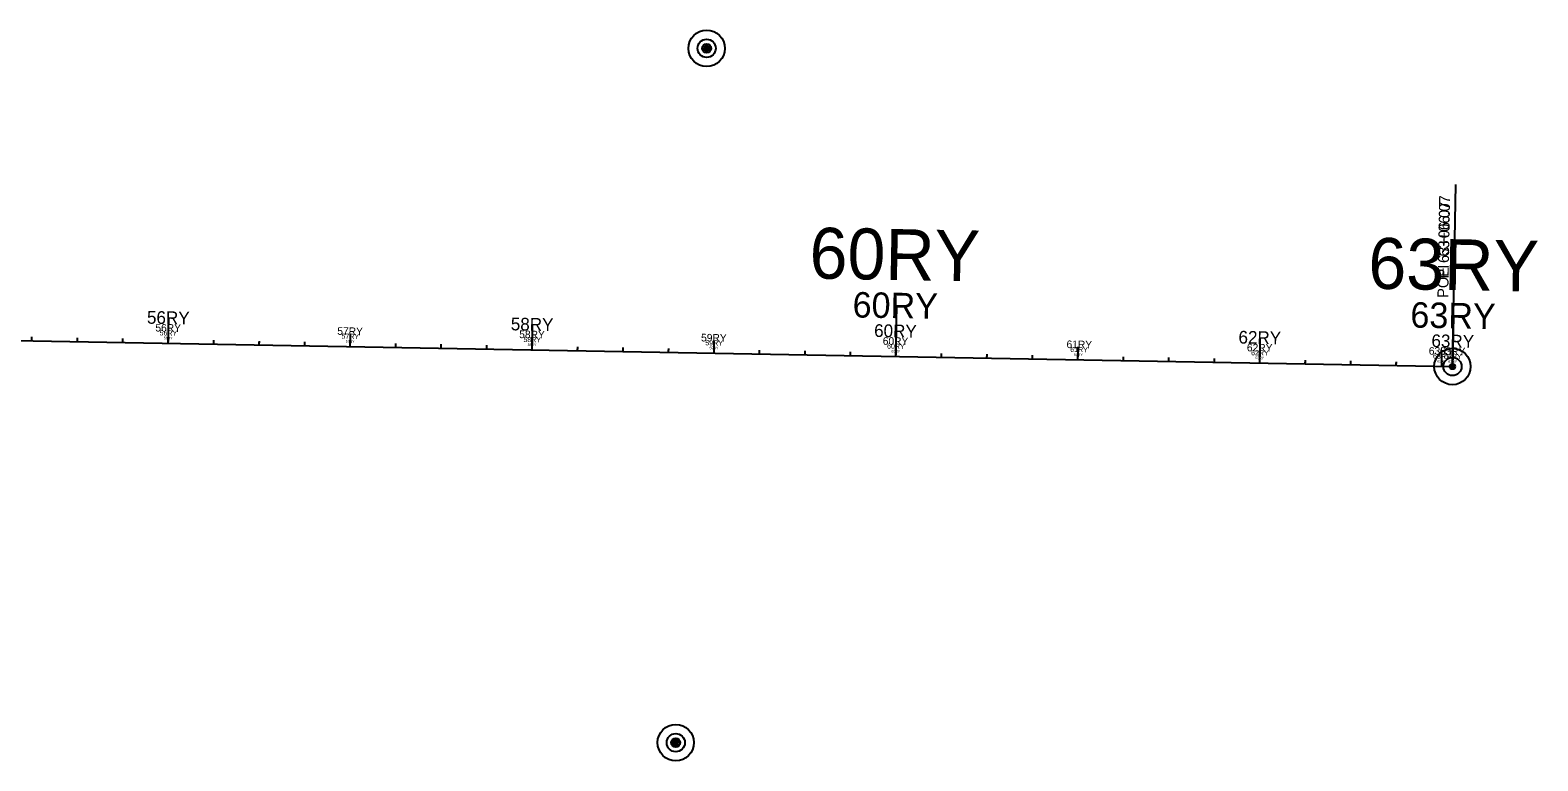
# Model space of a CAD drawing. Extents: x 564646 to 607088, y 225853 to 261760.
# Drawn here: x 599053 to 599882, y 238789 to 239190 of the extents above; entities that cross this region are included whole.
import ezdxf

# ---------------------------------------------------------------- set-up
doc = ezdxf.new("R2010")
doc.units = 0
for name, color, linetype in [('B_CONC_HIDDEN_LT', 7, 'Continuous'), ('B_CONST', 7, 'Continuous'), ('B_EXIST', 7, 'Continuous'), ('B_TEXT', 7, 'Continuous'), ('E-Easements', 7, 'Continuous'), ('E-Property Lines', 7, 'Continuous'), ('E_ALI_100', 7, 'Continuous'), ('E_RW_CorporateLimits', 7, 'Continuous'), ('E_RW_EasementUtility_Text', 7, 'Continuous'), ('E_WTR_FlowLine', 7, 'Continuous'), ('EMCS_SURVEY_PT CODES', 7, 'Continuous'), ('EMCS_SURVEY_PT ELEV', 7, 'Continuous'), ('EMCS_SURVEY_PT NOTES', 7, 'Continuous'), ('Level 33', 7, 'Continuous'), ('P-Easements Floodplain', 7, 'Continuous'), ('P-Easements Temporary', 7, 'Continuous'), ('P_ALI_100_Tic', 7, 'Continuous'), ('P_ALI_20', 7, 'Continuous'), ('P_ALI_50', 7, 'Continuous'), ('P_RW_AccessPreviousProject Txt', 7, 'Continuous'), ('P_RW_EasementPerm', 7, 'Continuous'), ('P_RW_PropertyConnector', 7, 'Continuous'), ('P_RW_Proposed', 7, 'Continuous'), ('P_WAL', 7, 'Continuous')]:
    doc.layers.add(name, color=color, linetype=linetype)

msp = doc.modelspace()

# ---------------------------------------------------------------- linework, layer by layer
at = {"layer": 'B_CONC_HIDDEN_LT'}
msp.add_line((597176.17, 239053.94), (599834.96, 239005.61), dxfattribs=at)
at = {"layer": 'B_CONST'}
for centre in [(599425.03, 239180.5), (599425.03, 239180.5), (599834.96, 239005.61), (599834.96, 239005.61), (599408.09, 238798.86), (599408.09, 238798.86)]:
    msp.add_circle(centre, 1.5, dxfattribs=at)
at = {"layer": 'B_EXIST'}
for centre in [(599425.03, 239180.5), (599834.96, 239005.61), (599408.09, 238798.86)]:
    msp.add_circle(centre, 5, dxfattribs=at)
at = {"layer": 'B_TEXT'}
msp.add_lwpolyline([(599834.96, 239005.61), (599836.78, 239105.59)], dxfattribs=at)
at = {"layer": 'E-Easements'}
for centre in [(599425.03, 239180.5), (599408.09, 238798.86)]:
    msp.add_circle(centre, 2.5, dxfattribs=at)
at = {"layer": 'E_ALI_100'}
for points in [[(599054.05, 239021.21), (599054.02, 239019.81)], [(599079.04, 239020.75), (599079.02, 239019.35)], [(599104.04, 239020.3), (599104.01, 239018.9)], [(599129.06, 239021.24), (599129.01, 239018.44)], [(599154.03, 239019.39), (599154, 239017.99)], [(599179.02, 239018.93), (599179, 239017.53)], [(599229.04, 239019.42), (599228.99, 239016.62)], [(599204.02, 239018.48), (599204, 239017.08)], [(599254.01, 239017.57), (599253.99, 239016.17)], [(599279.01, 239017.12), (599278.98, 239015.72)], [(599304, 239016.66), (599303.98, 239015.26)], [(599329.03, 239017.61), (599328.97, 239014.81)], [(599354, 239015.75), (599353.97, 239014.35)], [(599378.99, 239015.3), (599378.97, 239013.9)], [(599403.99, 239014.84), (599403.96, 239013.44)], [(599429.01, 239015.79), (599428.96, 239012.99)], [(599453.98, 239013.94), (599453.95, 239012.54)], [(599478.98, 239013.48), (599478.95, 239012.08)], [(599503.97, 239013.03), (599503.95, 239011.63)], [(599528.99, 239013.97), (599528.94, 239011.17)], [(599553.96, 239012.12), (599553.94, 239010.72)], [(599578.96, 239011.66), (599578.93, 239010.26)], [(599603.95, 239011.21), (599603.93, 239009.81)], [(599628.98, 239012.15), (599628.92, 239009.36)], [(599653.95, 239010.3), (599653.92, 239008.9)], [(599678.94, 239009.85), (599678.92, 239008.45)], [(599703.94, 239009.39), (599703.91, 239007.99)], [(599728.96, 239010.34), (599728.91, 239007.54)], [(599753.93, 239008.48), (599753.9, 239007.08)], [(599778.93, 239008.03), (599778.9, 239006.63)], [(599803.92, 239007.57), (599803.9, 239006.17)], [(599828.94, 239008.52), (599828.89, 239005.72)], [(599835.01, 239008.41), (599834.96, 239005.61)], [(599834.99, 239007.01), (599834.96, 239005.61)]]:
    msp.add_lwpolyline(points, dxfattribs=at)
at = {"layer": 'E_WTR_FlowLine'}
for centre in [(599425.03, 239180.5), (599834.96, 239005.61), (599408.09, 238798.86)]:
    msp.add_circle(centre, 0.5, dxfattribs=at)
at = {"layer": 'EMCS_SURVEY_PT CODES'}
msp.add_line((597176.17, 239053.94), (599834.96, 239005.61), dxfattribs=at)
at = {"layer": 'EMCS_SURVEY_PT ELEV'}
msp.add_line((597176.17, 239053.94), (599834.96, 239005.61), dxfattribs=at)
msp.add_line((597176.17, 239053.94), (599834.96, 239005.61), dxfattribs=at)
at = {"layer": 'Level 33'}
for points in [[(599054.03, 239020.51), (599054.02, 239019.81)], [(599079.03, 239020.05), (599079.02, 239019.35)], [(599104.02, 239019.6), (599104.01, 239018.9)], [(599129.03, 239019.84), (599129.01, 239018.44)], [(599154.02, 239018.69), (599154, 239017.99)], [(599179.01, 239018.23), (599179, 239017.53)], [(599204.01, 239017.78), (599204, 239017.08)], [(599229.02, 239018.02), (599228.99, 239016.62)], [(599254, 239016.87), (599253.99, 239016.17)], [(599279, 239016.42), (599278.98, 239015.72)], [(599303.99, 239015.96), (599303.98, 239015.26)], [(599329, 239016.21), (599328.97, 239014.81)], [(599353.98, 239015.05), (599353.97, 239014.35)], [(599378.98, 239014.6), (599378.97, 239013.9)], [(599403.97, 239014.14), (599403.96, 239013.44)], [(599428.98, 239014.39), (599428.96, 239012.99)], [(599453.97, 239013.24), (599453.95, 239012.54)], [(599478.96, 239012.78), (599478.95, 239012.08)], [(599503.96, 239012.33), (599503.95, 239011.63)], [(599528.97, 239012.57), (599528.94, 239011.17)], [(599553.95, 239011.42), (599553.94, 239010.72)], [(599578.95, 239010.96), (599578.93, 239010.26)], [(599628.95, 239010.75), (599628.92, 239009.36)], [(599603.94, 239010.51), (599603.93, 239009.81)], [(599653.93, 239009.6), (599653.92, 239008.9)], [(599678.93, 239009.15), (599678.92, 239008.45)], [(599703.93, 239008.69), (599703.91, 239007.99)], [(599728.93, 239008.94), (599728.91, 239007.54)], [(599753.92, 239007.78), (599753.9, 239007.08)], [(599778.91, 239007.33), (599778.9, 239006.63)], [(599803.91, 239006.87), (599803.9, 239006.17)], [(599828.92, 239007.12), (599828.89, 239005.72)], [(599834.99, 239007.01), (599834.96, 239005.61)], [(599834.97, 239006.31), (599834.96, 239005.61)]]:
    msp.add_lwpolyline(points, dxfattribs=at)
at = {"layer": 'P-Easements Floodplain'}
msp.add_line((597176.17, 239053.94), (599834.96, 239005.61), dxfattribs=at)
at = {"layer": 'P-Easements Temporary'}
for centre in [(599425.03, 239180.5), (599834.96, 239005.61), (599408.09, 238798.86)]:
    msp.add_circle(centre, 10, dxfattribs=at)
at = {"layer": 'P_ALI_100_Tic'}
for points in [[(599529.45, 239039.17), (599528.94, 239011.17)], [(599129.26, 239032.44), (599129.01, 239018.44)], [(599329.23, 239028.81), (599328.97, 239014.81)], [(599835.47, 239033.61), (599834.96, 239005.61)], [(599729.16, 239021.54), (599728.91, 239007.54)], [(599835.21, 239019.61), (599834.96, 239005.61)]]:
    msp.add_lwpolyline(points, dxfattribs=at)
at = {"layer": 'P_ALI_20'}
for points in [[(599129.13, 239025.44), (599129.01, 239018.44)], [(599229.12, 239023.62), (599228.99, 239016.62)], [(599329.1, 239021.81), (599328.97, 239014.81)], [(599429.09, 239019.99), (599428.96, 239012.99)], [(599529.2, 239025.17), (599528.94, 239011.17)], [(599835.21, 239019.61), (599834.96, 239005.61)], [(599629.05, 239016.35), (599628.92, 239009.36)], [(599729.04, 239014.54), (599728.91, 239007.54)], [(599829.02, 239012.72), (599828.89, 239005.72)], [(599835.09, 239012.61), (599834.96, 239005.61)]]:
    msp.add_lwpolyline(points, dxfattribs=at)
at = {"layer": 'P_ALI_50'}
msp.add_lwpolyline([(599834.96, 239005.61), (599836.78, 239105.59)], dxfattribs=at)
at = {"layer": 'P_RW_AccessPreviousProject Txt'}
for points in [[(599054.06, 239021.91), (599054.02, 239019.81)], [(599079.05, 239021.45), (599079.02, 239019.35)], [(599104.05, 239021), (599104.01, 239018.9)], [(599129.08, 239022.64), (599129.01, 239018.44)], [(599154.04, 239020.09), (599154, 239017.99)], [(599179.04, 239019.63), (599179, 239017.53)], [(599204.03, 239019.18), (599204, 239017.08)], [(599229.07, 239020.82), (599228.99, 239016.62)], [(599329.05, 239019.01), (599328.97, 239014.81)], [(599254.02, 239018.27), (599253.99, 239016.17)], [(599279.02, 239017.82), (599278.98, 239015.72)], [(599304.02, 239017.36), (599303.98, 239015.26)], [(599354.01, 239016.45), (599353.97, 239014.35)], [(599379, 239016), (599378.97, 239013.9)], [(599404, 239015.54), (599403.96, 239013.44)], [(599429.03, 239017.19), (599428.96, 239012.99)], [(599453.99, 239014.64), (599453.95, 239012.54)], [(599478.99, 239014.18), (599478.95, 239012.08)], [(599503.98, 239013.73), (599503.95, 239011.63)], [(599529.02, 239015.37), (599528.94, 239011.17)], [(599553.98, 239012.82), (599553.94, 239010.72)], [(599578.97, 239012.36), (599578.93, 239010.26)], [(599603.97, 239011.91), (599603.93, 239009.81)], [(599629, 239013.55), (599628.92, 239009.36)], [(599653.96, 239011), (599653.92, 239008.9)], [(599728.98, 239011.74), (599728.91, 239007.54)], [(599678.95, 239010.55), (599678.92, 239008.45)], [(599703.95, 239010.09), (599703.91, 239007.99)], [(599753.94, 239009.18), (599753.9, 239007.08)], [(599778.94, 239008.73), (599778.9, 239006.63)], [(599803.93, 239008.27), (599803.9, 239006.17)], [(599828.97, 239009.92), (599828.89, 239005.72)], [(599835.04, 239009.81), (599834.96, 239005.61)], [(599835, 239007.71), (599834.96, 239005.61)]]:
    msp.add_lwpolyline(points, dxfattribs=at)
at = {"layer": 'P_RW_EasementPerm'}
for points in [[(599129.13, 239025.44), (599129.01, 239018.44)], [(599229.05, 239020.12), (599228.99, 239016.62)], [(599329.1, 239021.81), (599328.97, 239014.81)], [(599429.02, 239016.49), (599428.96, 239012.99)], [(599529.07, 239018.17), (599528.94, 239011.17)], [(599628.99, 239012.85), (599628.92, 239009.36)], [(599729.04, 239014.54), (599728.91, 239007.54)], [(599835.09, 239012.61), (599834.96, 239005.61)], [(599828.96, 239009.22), (599828.89, 239005.72)], [(599835.02, 239009.11), (599834.96, 239005.61)]]:
    msp.add_lwpolyline(points, dxfattribs=at)
at = {"layer": 'P_RW_PropertyConnector'}
msp.add_line((597176.17, 239053.94), (599834.96, 239005.61), dxfattribs=at)
at = {"layer": 'P_WAL'}
for centre in [(599425.03, 239180.5), (599834.96, 239005.61), (599408.09, 238798.86)]:
    msp.add_circle(centre, 1, dxfattribs=at)

# ---------------------------------------------------------------- texts
for s, p in [('56RY', (599124.37, 239022.73)), ('57RY', (599224.35, 239020.91)), ('58RY', (599324.33, 239019.09)), ('59RY', (599424.3, 239017.28)), ('60RY', (599524.19, 239015.46)), ('61RY', (599624.86, 239013.63)), ('62RY', (599724.27, 239011.82)), ('63RY', (599824.25, 239010.01)), ('63RY', (599830.32, 239009.9))]:
    msp.add_text(s, height=2.8, rotation=358.95862).set_placement(p)
at = {"layer": 'B_TEXT'}
msp.add_text('POE 63+06.07', height=6, rotation=88.95862, dxfattribs=at).set_placement((599832.64, 239043.3))
at = {"layer": 'E-Property Lines'}
for s, p in [('60RY', (599481.43, 239054.04)), ('63RY', (599788.55, 239048.46))]:
    msp.add_text(s, height=28, rotation=358.95862, dxfattribs=at).set_placement(p)
at = {"layer": 'E_RW_CorporateLimits'}
for s, p in [('60RY', (599505.19, 239032.61)), ('63RY', (599811.76, 239027.04))]:
    msp.add_text(s, height=14, rotation=358.95862, dxfattribs=at).set_placement(p)
at = {"layer": 'E_RW_EasementUtility_Text'}
for s, p in [('56RY', (599126.69, 239020.58)), ('57RY', (599226.67, 239018.77)), ('58RY', (599326.65, 239016.95)), ('59RY', (599426.63, 239015.13)), ('60RY', (599526.57, 239013.32)), ('61RY', (599626.89, 239011.49)), ('62RY', (599726.59, 239009.68)), ('63RY', (599826.57, 239007.86)), ('63RY', (599832.64, 239007.75))]:
    msp.add_text(s, height=1.4, rotation=358.95862, dxfattribs=at).set_placement(p)
at = {"layer": 'EMCS_SURVEY_PT NOTES'}
for s, p in [('56RY', (599122.05, 239024.87)), ('57RY', (599222.03, 239023.05)), ('58RY', (599322.01, 239021.24)), ('59RY', (599421.96, 239019.42)), ('60RY', (599521.81, 239017.6)), ('61RY', (599622.82, 239015.77)), ('62RY', (599721.95, 239013.97)), ('63RY', (599821.93, 239012.15)), ('63RY', (599828, 239012.04))]:
    msp.add_text(s, height=4.2, rotation=358.95862, dxfattribs=at).set_placement(p)
at = {"layer": 'P_ALI_50'}
msp.add_text('PI  63+06.07', height=6, rotation=88.95862, dxfattribs=at).set_placement((599832.84, 239053.97))
at = {"layer": 'P_RW_Proposed'}
for s, p in [('56RY', (599117.41, 239029.16)), ('58RY', (599317.37, 239025.52)), ('60RY', (599517.06, 239021.89)), ('62RY', (599717.31, 239018.25)), ('63RY', (599823.36, 239016.32))]:
    msp.add_text(s, height=7, rotation=358.95862, dxfattribs=at).set_placement(p)

doc.saveas('drawing.dxf')
